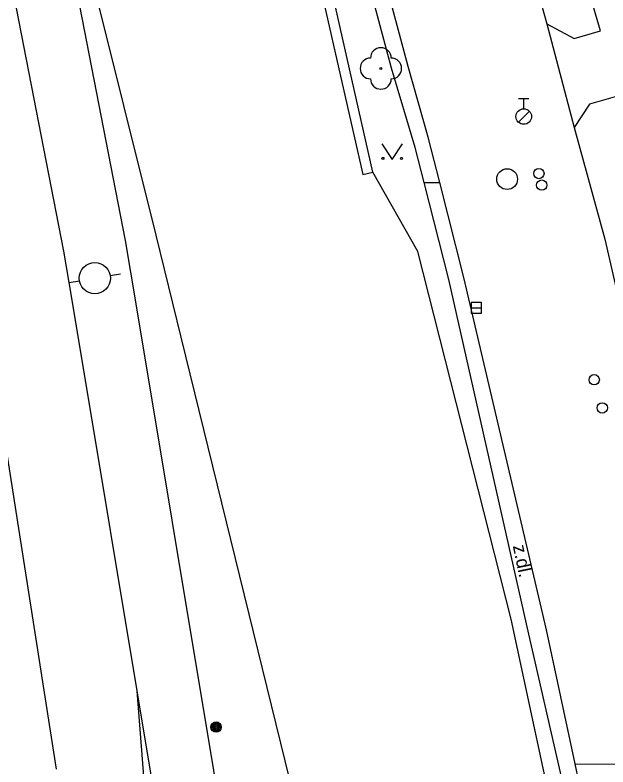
# Model space of a CAD drawing. Extents: x -596229 to -595156, y -1161237 to -1159376.
# Drawn here: x -595936.1 to -595907.51, y -1161090.38 to -1161054.1 of the extents above; entities that cross this region are included whole.
import ezdxf

# ---------------------------------------------------------------- set-up
doc = ezdxf.new("R2010")
doc.units = 0
for name, color, linetype in [('Level 12', 7, 'Continuous'), ('Level 22', 7, 'Continuous'), ('Level 25', 7, 'Continuous'), ('Level 27', 7, 'Continuous'), ('Level 28', 7, 'Continuous'), ('Level 36', 7, 'Continuous'), ('Specificka linie pasportu komunikaci', 7, 'Continuous'), ('TM - CD - osa koleji', 7, 'Continuous'), ('TM - chodniky - VP', 7, 'Continuous'), ('TM - horni hrana svahu', 7, 'Continuous'), ('TM - komunikace - VP', 7, 'Continuous'), ('TM - letecke snimky - pomocna linie', 7, 'Continuous'), ('TM - plot zdeny_ ohradni zed - VP', 7, 'Continuous'), ('TM - popis povrchu', 7, 'Continuous'), ('TM - rozhrani ploch obecne - VP', 7, 'Continuous')]:
    doc.layers.add(name, color=color, linetype=linetype)

msp = doc.modelspace()

# ---------------------------------------------------------------- linework, layer by layer
at = {"layer": 'Level 12'}
for p, q in [((-595931.519, -1161066.673), (-595931.026, -1161066.588)), ((-595933.49, -1161067.01), (-595932.997, -1161066.926))]:
    msp.add_line(p, q, dxfattribs=at)
msp.add_circle((-595932.258, -1161066.799), 0.75, dxfattribs=at)
at = {"layer": 'Level 22'}
msp.add_circle((-595918.46, -1161056.68), 0.05, dxfattribs=at)
for centre, start, end in [((-595918.46, -1161056.18), 0, 180), ((-595918.96, -1161056.68), 90, 270), ((-595917.96, -1161056.68), 270, 90), ((-595918.46, -1161057.18), 180, 0)]:
    msp.add_arc(centre, 0.5, start, end, dxfattribs=at)
at = {"layer": 'Level 25'}
for radius in [0.25, 0.2, 0.15, 0.1, 0.05]:
    msp.add_circle((-595926.41, -1161088.46), radius, dxfattribs=at)
at = {"layer": 'Level 27'}
msp.add_line((-595914.1, -1161068.23), (-595913.6, -1161068.23), dxfattribs=at)
msp.add_lwpolyline([(-595914.1, -1161068.48), (-595913.6, -1161068.48), (-595913.6, -1161067.98), (-595914.1, -1161067.98)], close=True, dxfattribs=at)
msp.add_circle((-595912.37, -1161062.02), 0.5, dxfattribs=at)
at = {"layer": 'Level 28'}
for p, q in [((-595911.82, -1161058.125), (-595911.32, -1161058.125)), ((-595911.57, -1161058.625), (-595911.57, -1161058.125)), ((-595911.828, -1161059.272), (-595911.298, -1161058.742))]:
    msp.add_line(p, q, dxfattribs=at)
for centre, radius in [((-595911.57, -1161059), 0.375), ((-595910.84, -1161061.75), 0.25), ((-595910.7, -1161062.31), 0.25), ((-595908.17, -1161071.7), 0.25), ((-595907.78, -1161073.06), 0.25)]:
    msp.add_circle(centre, radius, dxfattribs=at)
at = {"layer": 'Level 36'}
msp.add_lwpolyline([(-595918.41, -1161060.32), (-595917.91, -1161061.07), (-595917.41, -1161060.32)], dxfattribs=at)
for centre in [(-595918.36, -1161061.02), (-595917.461, -1161061.02)]:
    msp.add_circle(centre, 0.05, dxfattribs=at)
at = {"layer": 'Specificka linie pasportu komunikaci'}
for points in [[(-595916.37, -1161062.19), (-595915.62, -1161062.19)], [(-595909.09, -1161090.24), (-595902, -1161090.25)]]:
    msp.add_lwpolyline(points, dxfattribs=at)
at = {"layer": 'TM - CD - osa koleji'}
for points in [[(-595932.77, -1161071.33), (-595933.49, -1161067.01), (-595933.75, -1161065.49), (-595936.27, -1161052.51), (-595940.76, -1161033.53), (-595944.99, -1161018.31), (-595952.18, -1160995.78), (-595964.08, -1160961.74), (-595973.9, -1160934.08), (-595976.55, -1160926.59), (-595979.47, -1160918.46), (-595984.79, -1160903.55)], [(-595930.21, -1161086.71), (-595932.77, -1161071.33)], [(-595934.1, -1161090.49), (-595936.88, -1161072.82)], [(-595927.57, -1161133.94), (-595927.96, -1161118.84), (-595928.04, -1161117.22), (-595928.65, -1161106.69), (-595930.21, -1161086.71)], [(-595920.45, -1161151.42), (-595921.03, -1161145.95), (-595922.82, -1161133.24), (-595926.94, -1161106.48), (-595930.21, -1161086.71)]]:
    msp.add_lwpolyline(points, dxfattribs=at)
at = {"layer": 'TM - chodniky - VP'}
for points in [[(-595910.45, -1161054.52), (-595909.13, -1161055.23), (-595907.86, -1161054.87), (-595909.68, -1161048.66)], [(-595905.75, -1161073.11), (-595904.69, -1161073.74), (-595902.67, -1161073.27), (-595905.21, -1161064.17), (-595906.94, -1161057.98), (-595908.4, -1161058.4), (-595909.14, -1161059.53)]]:
    msp.add_lwpolyline(points, dxfattribs=at)
at = {"layer": 'TM - horni hrana svahu'}
for points in [[(-595928.09, -1161069.64), (-595929.3, -1161064.73), (-595935.52, -1161039.74), (-595946.19, -1161003.54), (-595961.27, -1160959.66), (-595971.33, -1160931.82), (-595976.13, -1160918.19), (-595979.12, -1160909.99)], [(-595912.2, -1161142.74), (-595912.63, -1161140.54), (-595919.36, -1161105.22), (-595928.09, -1161069.64)]]:
    msp.add_lwpolyline(points, dxfattribs=at)
at = {"layer": 'TM - komunikace - VP'}
for points in [[(-595916.8, -1161060.49), (-595917.94, -1161056.66), (-595920.09, -1161048.66)], [(-595912.1, -1161048.66), (-595910.45, -1161054.52)], [(-595910.45, -1161054.52), (-595909.14, -1161059.53)], [(-595909.14, -1161059.53), (-595907.66, -1161064.91), (-595906.45, -1161070.17), (-595906.17, -1161070.15), (-595906, -1161070.69), (-595906.21, -1161071.14), (-595905.75, -1161073.11)], [(-595916.37, -1161062.19), (-595916.8, -1161060.49)], [(-595908.56, -1161096.33), (-595908.88, -1161094.65), (-595911.32, -1161083.98), (-595915.18, -1161066.86), (-595916.37, -1161062.19)]]:
    msp.add_lwpolyline(points, dxfattribs=at)
at = {"layer": 'TM - letecke snimky - pomocna linie'}
msp.add_lwpolyline([(-595937.84, -1161032.84), (-595935.68, -1161041.99), (-595933.35, -1161051.82), (-595930.79, -1161064.98), (-595930.53, -1161066.51), (-595929.81, -1161070.84), (-595927.25, -1161086.21), (-595927.21, -1161086.48), (-595925.17, -1161098.79), (-595925.11, -1161099.16), (-595923.98, -1161106.01), (-595919.85, -1161132.8), (-595919.58, -1161134.76), (-595919.53, -1161135.06), (-595918.06, -1161145.53), (-595918.05, -1161145.64), (-595917.54, -1161150.42)], dxfattribs=at)
at = {"layer": 'TM - plot zdeny_ ohradni zed - VP'}
msp.add_lwpolyline([(-595922.27, -1161048.82), (-595919.33, -1161061.8), (-595918.84, -1161061.69)], dxfattribs=at)
at = {"layer": 'TM - rozhrani ploch obecne - VP'}
for points in [[(-595918.84, -1161061.69), (-595921.78, -1161048.7)], [(-595916.18, -1161059.99), (-595917.14, -1161056.59), (-595919.26, -1161048.66)], [(-595915.62, -1161062.19), (-595916.18, -1161059.99)], [(-595916.68, -1161065.51), (-595918.84, -1161061.69)], [(-595914.46, -1161066.77), (-595915.62, -1161062.19)], [(-595912.17, -1161083.26), (-595916.68, -1161065.51)], [(-595910.47, -1161083.77), (-595914.46, -1161066.77)], [(-595909.69, -1161094.86), (-595912.17, -1161083.26)], [(-595909.09, -1161090.24), (-595910.47, -1161083.77)], [(-595908.2, -1161094.41), (-595909.09, -1161090.24)]]:
    msp.add_lwpolyline(points, dxfattribs=at)

# ---------------------------------------------------------------- texts
at = {"layer": 'TM - popis povrchu'}
msp.add_text('z.dl.', height=0.65, rotation=281.76, dxfattribs=at).set_placement((-595912.1, -1161079.72))

doc.saveas('drawing.dxf')
